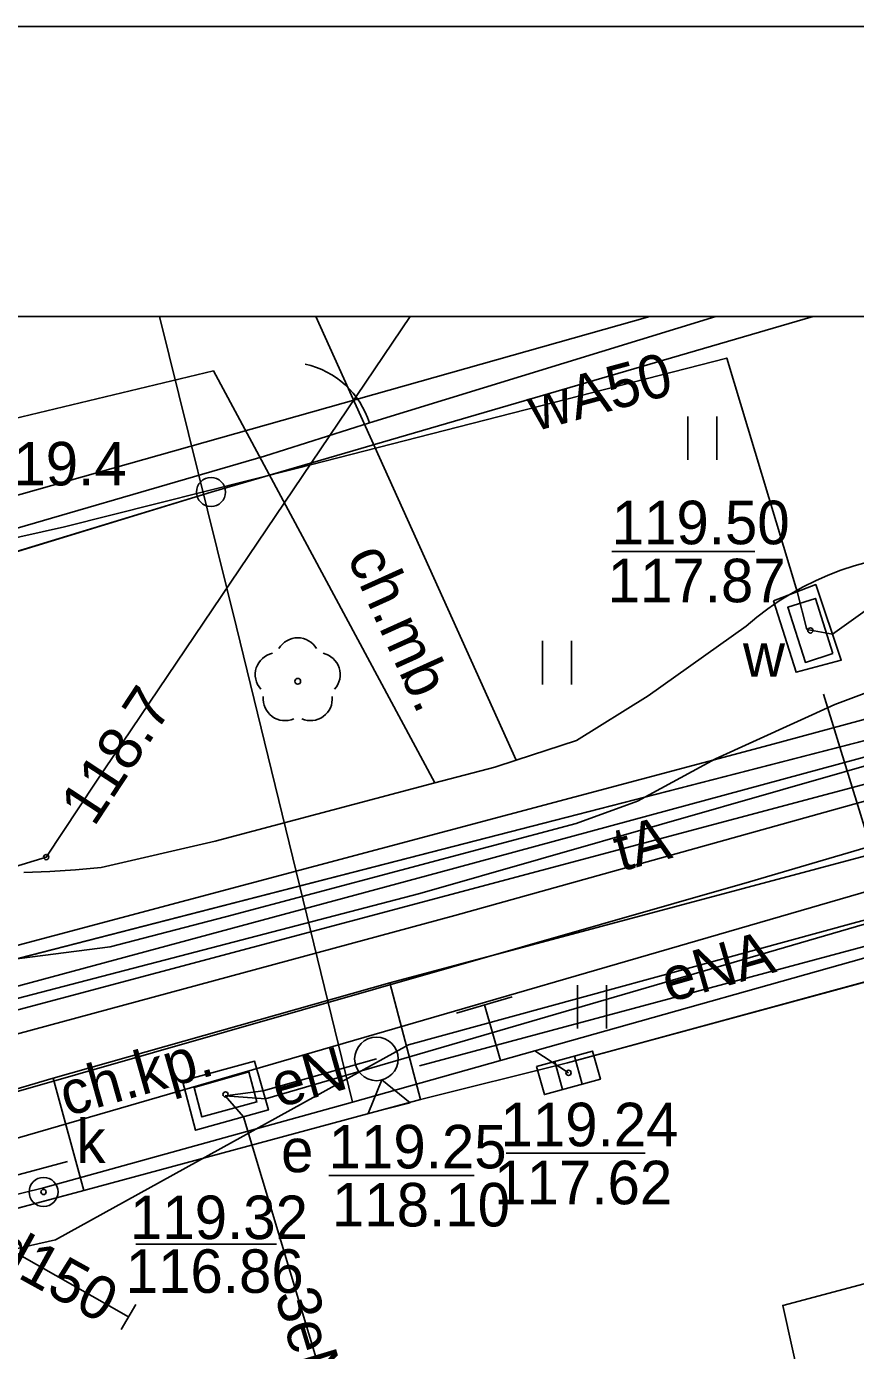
# Model space of a CAD drawing. Extents: x 6432121 to 6432331, y 5662538 to 5662686.
# Drawn here: x 6432203.86 to 6432218.14, y 5662663.23 to 5662686.05 of the extents above; entities that cross this region are included whole.
import ezdxf

# ---------------------------------------------------------------- set-up
doc = ezdxf.new("R2010")
doc.units = 0
for name, color, linetype in [('Warstwa 1', 7, 'Continuous'), ('Warstwa 10', 7, 'Continuous'), ('Warstwa 11', 7, 'Continuous'), ('Warstwa 12', 7, 'Continuous'), ('Warstwa 13', 7, 'Continuous'), ('Warstwa 14', 7, 'Continuous'), ('Warstwa 15', 7, 'Continuous'), ('Warstwa 16', 7, 'Continuous'), ('Warstwa 19', 7, 'Continuous'), ('Warstwa 2', 7, 'Continuous'), ('Warstwa 20', 7, 'Continuous'), ('Warstwa 3', 7, 'Continuous'), ('Warstwa 4', 7, 'Continuous'), ('Warstwa 40', 7, 'Continuous'), ('Warstwa 5', 7, 'Continuous'), ('Warstwa 6', 7, 'Continuous'), ('Warstwa 63', 7, 'Continuous'), ('Warstwa 8', 7, 'Continuous'), ('Warstwa 9', 7, 'Continuous')]:
    doc.layers.add(name, color=color, linetype=linetype)

msp = doc.modelspace()

# ---------------------------------------------------------------- linework, layer by layer
at = {"layer": 'Warstwa 1'}
for p, q in [((6432207.04, 5662678.03), (6432217.416, 5662681.053)), ((6432207.04, 5662678.03), (6432217.416, 5662681.053)), ((6432136.78, 5662656.51), (6432207.04, 5662678.03)), ((6432136.78, 5662656.51), (6432207.04, 5662678.03)), ((6432183.398, 5662664.76), (6432232.544, 5662677.413)), ((6432183.398, 5662664.76), (6432232.544, 5662677.413))]:
    msp.add_line(p, q, dxfattribs=at)
at = {"layer": 'Warstwa 10'}
for points in [[(6432178.835, 5662663.483), (6432179.667, 5662663.685), (6432183.376, 5662664.411), (6432187.121, 5662665.475), (6432194.656, 5662667.652), (6432202.136, 5662669.801), (6432216.655, 5662673.667), (6432220.668, 5662674.754), (6432223.415, 5662675.469), (6432239.794, 5662679.846), (6432240.486, 5662681.053)], [(6432125.976, 5662657.54), (6432137.66, 5662651.5), (6432142.32, 5662652.91), (6432165.05, 5662658.98), (6432185.52, 5662663.77), (6432211.24, 5662670.73), (6432230.88, 5662676.21), (6432235.66, 5662674.65)]]:
    msp.add_lwpolyline(points, dxfattribs=at)
msp.add_circle((6432207.04, 5662678.03), 0.25, dxfattribs=at)
at = {"layer": 'Warstwa 11'}
msp.add_circle((6432208.534, 5662674.768), 0.05, dxfattribs=at)
for centre, start, end in [((6432208.534, 5662675.143), 30.1471, 149.8529), ((6432208.177, 5662674.884), 102.1471, 221.8529), ((6432208.891, 5662674.884), 318.1471, 77.8529), ((6432208.314, 5662674.465), 174.1471, 293.8529), ((6432208.754, 5662674.465), 246.1471, 5.8529)]:
    msp.add_arc(centre, 0.375, start, end, dxfattribs=at)
at = {"layer": 'Warstwa 12'}
for points in [[(6432210.47, 5662681.053), (6432205.055, 5662673.029), (6432204.2, 5662671.738), (6432181.234, 5662664.72), (6432157.763, 5662657.531), (6432142.635, 5662652.934), (6432138.113, 5662652.263), (6432131.596, 5662652.74), (6432125.976, 5662654.881)], [(6432252.82, 5662681.053), (6432221.047, 5662671.933), (6432138.764, 5662648.032), (6432132.495, 5662646.498), (6432126.708, 5662647.568), (6432125.976, 5662647.734)], [(6432236.687, 5662681.053), (6432236.179, 5662680.268), (6432235.997, 5662679.964), (6432233.762, 5662674.712), (6432226.676, 5662672.867), (6432218.17, 5662670.615), (6432210.443, 5662668.5), (6432204.363, 5662665.144), (6432201.056, 5662664.395), (6432197.485, 5662663.542), (6432196.233, 5662663.213), (6432189.469, 5662661.315), (6432178.042, 5662658.146), (6432174.146, 5662657.07), (6432174.002, 5662656.976), (6432170.36, 5662653.903), (6432162.21, 5662651.482), (6432158.665, 5662650.451), (6432153.815, 5662649.037)], [(6432161.551, 5662681.053), (6432167.819, 5662674.322), (6432168.955, 5662673.173), (6432173.894, 5662667.86), (6432175.535, 5662666.115), (6432175.942, 5662663.535), (6432176.507, 5662663.465), (6432178.7, 5662662.668), (6432179.059, 5662662.663), (6432183.548, 5662663.582), (6432184.625, 5662663.866), (6432192.37, 5662666.167), (6432200.892, 5662668.754), (6432210.964, 5662671.473), (6432222.171, 5662674.51), (6432232.177, 5662677.188), (6432233.223, 5662677.473), (6432238.797, 5662677.192), (6432240.154, 5662672.977), (6432241.644, 5662668.194), (6432242.191, 5662665.717), (6432243.645, 5662658.765)], [(6432214.6, 5662681.053), (6432203.235, 5662677.843), (6432183.955, 5662671.923), (6432183.557, 5662671.545)], [(6432248.82, 5662629.93), (6432248.54, 5662629.72), (6432247.48, 5662630.2), (6432247.186, 5662630.33), (6432247.012, 5662630.407), (6432246.73, 5662630.84), (6432246.374, 5662630.582), (6432219.55, 5662620.66), (6432213.49, 5662610.33), (6432213.18, 5662609.798), (6432212.84, 5662609.97), (6432201.94, 5662619.39), (6432188.48, 5662659.63), (6432188.372, 5662660.264), (6432188.26, 5662660.96), (6432187.54, 5662663.58), (6432189.456, 5662664.144), (6432190.073, 5662664.038), (6432190.591, 5662664.478), (6432199.77, 5662667.18), (6432202.78, 5662668.86), (6432236.07, 5662677.73), (6432238.751, 5662681.053)], [(6432206.153, 5662681.053), (6432207.481, 5662675.701), (6432209.479, 5662667.515)], [(6432225.358, 5662681.053), (6432223.45, 5662679.654), (6432217.748, 5662675.581), (6432217.308, 5662675.659)], [(6432217.308, 5662675.659), (6432217.142, 5662676.313), (6432215.927, 5662680.339), (6432208.528, 5662678.44), (6432204.518, 5662677.431), (6432201.816, 5662676.824), (6432201.263, 5662678.637)], [(6432250.716, 5662679.086), (6432250.106, 5662678.913), (6432243.339, 5662677.004), (6432243.112, 5662676.943), (6432234.209, 5662674.451), (6432226.12, 5662672.203), (6432219.693, 5662670.39), (6432212.03, 5662668.231), (6432209.479, 5662667.515)], [(6432126.82, 5662648.145), (6432127.178, 5662648.008), (6432131.097, 5662647.505), (6432133.122, 5662647.201), (6432135.028, 5662647.845), (6432148.121, 5662651.554), (6432159.913, 5662655.046), (6432176.332, 5662659.768), (6432190.085, 5662663.807), (6432202.171, 5662667.26), (6432216.316, 5662671.31), (6432225.518, 5662674.016), (6432231.508, 5662675.69), (6432243.068, 5662679.006)], [(6432129.02, 5662644.49), (6432128.8, 5662645.29), (6432133.76, 5662648.23), (6432151.52, 5662653.14), (6432168.26, 5662658.24), (6432174.11, 5662659.65), (6432182.72, 5662662.19), (6432184.64, 5662664.15), (6432186.13, 5662664.58), (6432196.49, 5662667.42), (6432210.64, 5662671.11), (6432218.98, 5662673.5), (6432219.48, 5662674.07), (6432230.96, 5662676.8), (6432232.45, 5662677.97)], [(6432232.59, 5662674.745), (6432231.97, 5662674.57), (6432207.98, 5662667.57), (6432207.285, 5662667.626)], [(6432217.592, 5662674.545), (6432218.677, 5662671.027), (6432220.558, 5662664.988)], [(6432213.2, 5662668.02), (6432212.621, 5662668.398)], [(6432207.285, 5662667.626), (6432207.94, 5662667.71), (6432209.89, 5662668.26)], [(6432125.976, 5662645.74), (6432131.623, 5662647.083), (6432138.492, 5662648.808), (6432146.028, 5662650.541), (6432153.864, 5662652.39), (6432160.763, 5662654.062), (6432162.516, 5662654.48), (6432167.591, 5662655.857), (6432175.21, 5662658.015), (6432175.71, 5662658.12), (6432181.929, 5662659.868), (6432191.24, 5662662.505), (6432195.372, 5662663.644), (6432202.44, 5662665.619), (6432204.153, 5662666.037), (6432209.479, 5662667.515)], [(6432207.285, 5662667.626), (6432207.6, 5662667.26), (6432209.85, 5662659.78), (6432209.785, 5662659.335)], [(6432202.44, 5662665.619), (6432205.619, 5662663.813)], [(6432220.558, 5662664.988), (6432216.892, 5662664.011), (6432217.526, 5662661.155)]]:
    msp.add_lwpolyline(points, dxfattribs=at)
at = {"layer": 'Warstwa 14'}
for p, q in [((6432213.947, 5662677.005), (6432216.41, 5662677.005)), ((6432214.519, 5662666.635), (6432212.127, 5662666.635)), ((6432209.072, 5662666.248), (6432211.574, 5662666.248)), ((6432205.743, 5662665.068), (6432208.166, 5662665.068))]:
    msp.add_line(p, q, dxfattribs=at)
for centre in [(6432217.367, 5662675.645), (6432217.367, 5662675.645), (6432204.2, 5662671.738), (6432213.2, 5662668.02), (6432207.29, 5662667.647), (6432204.155, 5662665.967), (6432204.155, 5662665.967)]:
    msp.add_circle(centre, 0.045, dxfattribs=at)
at = {"layer": 'Warstwa 16'}
for points in [[(6432216.733, 5662676.157), (6432217.46, 5662676.436), (6432217.899, 5662675.132), (6432217.122, 5662674.923)], [(6432206.55, 5662667.88), (6432207.79, 5662668.22), (6432208.03, 5662667.38), (6432206.77, 5662667.03)]]:
    msp.add_lwpolyline(points, close=True, dxfattribs=at)
at = {"layer": 'Warstwa 19'}
for p, q in [((6432211.27, 5662669.051), (6432212.23, 5662669.331)), ((6432212.03, 5662668.231), (6432211.75, 5662669.191))]:
    msp.add_line(p, q, dxfattribs=at)
at = {"layer": 'Warstwa 2'}
for points in [[(6432209.77, 5662679.22), (6432215.737, 5662681.053)], [(6432201.9, 5662678.817), (6432202.47, 5662677.05), (6432207.96, 5662678.65)], [(6432210.63, 5662668.14), (6432237.94, 5662675.47), (6432239.56, 5662678.35)], [(6432204.57, 5662666.49), (6432179.48, 5662659.74), (6432149.1, 5662650.42)]]:
    msp.add_lwpolyline(points, dxfattribs=at)
at = {"layer": 'Warstwa 20'}
msp.add_line((6432205.745, 5662664.029), (6432205.493, 5662663.597), dxfattribs=at)
at = {"layer": 'Warstwa 3'}
msp.add_lwpolyline([(6432207.96, 5662678.65), (6432209.77, 5662679.22)], dxfattribs=at)
msp.add_arc((6432208.339, 5662678.769), 1.5, 17.4814, 77.4814, dxfattribs=at)
at = {"layer": 'Warstwa 4'}
for p, q in [((6432212.965, 5662668.214), (6432213.098, 5662667.732)), ((6432213.302, 5662668.308), (6432213.435, 5662667.826))]:
    msp.add_line(p, q, dxfattribs=at)
for points in [[(6432217.757, 5662675.245), (6432217.453, 5662676.197), (6432216.977, 5662676.045), (6432217.281, 5662675.093)], [(6432212.651, 5662668.127), (6432213.615, 5662668.395), (6432213.749, 5662667.913), (6432212.785, 5662667.645)], [(6432206.75, 5662667.77), (6432207.69, 5662668.04), (6432207.83, 5662667.52), (6432206.88, 5662667.26)]]:
    msp.add_lwpolyline(points, close=True, dxfattribs=at)
msp.add_circle((6432204.155, 5662665.967), 0.25, dxfattribs=at)
at = {"layer": 'Warstwa 40'}
msp.add_lwpolyline([(6432209.983, 5662667.897), (6432210.471, 5662667.506), (6432209.745, 5662667.319)], close=True, dxfattribs=at)
msp.add_circle((6432209.89, 5662668.26), 0.375, dxfattribs=at)
at = {"layer": 'Warstwa 5'}
for p, q in [((6432208.846, 5662681.053), (6432212.299, 5662673.411)), ((6432203.254, 5662679.202), (6432207.083, 5662680.119)), ((6432207.083, 5662680.119), (6432210.898, 5662673.016)), ((6432215.254, 5662678.584), (6432215.254, 5662679.334)), ((6432215.754, 5662678.584), (6432215.754, 5662679.334)), ((6432218.12, 5662676.76), (6432223.92, 5662678.34)), ((6432217.454, 5662676.5), (6432217.672, 5662676.597)), ((6432217.672, 5662676.597), (6432217.894, 5662676.684)), ((6432217.894, 5662676.684), (6432218.12, 5662676.76)), ((6432217.032, 5662676.277), (6432217.241, 5662676.394)), ((6432217.241, 5662676.394), (6432217.454, 5662676.5)), ((6432216.633, 5662676.017), (6432216.83, 5662676.152)), ((6432216.83, 5662676.152), (6432217.032, 5662676.277)), ((6432216.26, 5662675.72), (6432216.443, 5662675.873)), ((6432216.443, 5662675.873), (6432216.633, 5662676.017)), ((6432214.57, 5662674.52), (6432216.26, 5662675.72)), ((6432212.752, 5662674.715), (6432212.752, 5662675.465)), ((6432213.252, 5662674.715), (6432213.252, 5662675.465)), ((6432213.18, 5662668.19), (6432238.51, 5662675.09)), ((6432213.18, 5662668.19), (6432238.51, 5662675.09)), ((6432213.34, 5662673.75), (6432214.57, 5662674.52)), ((6432210.12, 5662669.57), (6432225.69, 5662673.73)), ((6432210.12, 5662669.57), (6432225.69, 5662673.73)), ((6432212.299, 5662673.411), (6432213.34, 5662673.75)), ((6432207.11, 5662672.01), (6432210.898, 5662673.016)), ((6432205.15, 5662671.56), (6432207.11, 5662672.01)), ((6432204.706, 5662671.518), (6432205.15, 5662671.56)), ((6432203.816, 5662671.471), (6432204.261, 5662671.488)), ((6432204.261, 5662671.488), (6432204.706, 5662671.518)), ((6432204.32, 5662667.93), (6432210.12, 5662669.57)), ((6432210.12, 5662669.57), (6432210.65, 5662667.56)), ((6432213.354, 5662668.783), (6432213.354, 5662669.533)), ((6432213.854, 5662668.783), (6432213.854, 5662669.533)), ((6432210.65, 5662667.56), (6432213.18, 5662668.19)), ((6432210.65, 5662667.56), (6432213.18, 5662668.19)), ((6432127.12, 5662644.89), (6432204.32, 5662667.93)), ((6432204.85, 5662665.99), (6432210.65, 5662667.56)), ((6432198.79, 5662664.37), (6432204.85, 5662665.99))]:
    msp.add_line(p, q, dxfattribs=at)
at = {"layer": 'Warstwa 6'}
for points in [[(6432139.86, 5662681.053), (6432132.84, 5662660.45), (6432136.78, 5662656.51), (6432207.04, 5662678.03), (6432217.416, 5662681.053)], [(6432217.416, 5662681.053), (6432207.04, 5662678.03), (6432136.78, 5662656.51), (6432134.43, 5662655.74), (6432136.954, 5662653.004), (6432164.325, 5662660.371), (6432183.398, 5662664.76), (6432232.544, 5662677.413), (6432235.366, 5662681.053)], [(6432164.06, 5662654.4), (6432171.72, 5662656.75), (6432178.39, 5662658.77), (6432185.89, 5662660.86), (6432198.79, 5662664.37), (6432204.85, 5662665.99), (6432210.65, 5662667.56), (6432213.18, 5662668.19), (6432238.51, 5662675.09), (6432238.854, 5662675.652), (6432239.185, 5662676.222), (6432239.503, 5662676.799), (6432239.808, 5662677.384), (6432240.099, 5662677.975), (6432240.377, 5662678.572), (6432240.642, 5662679.176), (6432240.893, 5662679.785), (6432241.13, 5662680.4), (6432241.403, 5662681.053)]]:
    msp.add_lwpolyline(points, dxfattribs=at)
msp.add_lwpolyline([(6432234.842, 5662644.244), (6432245.39, 5662639.916), (6432244.087, 5662648.722), (6432241.262, 5662679.658), (6432232.544, 5662677.413), (6432183.398, 5662664.76), (6432164.325, 5662660.371), (6432136.954, 5662653.004), (6432141.907, 5662600.47), (6432147.05, 5662605.45), (6432164.332, 5662622.19), (6432166.394, 5662623.975)], close=True, dxfattribs=at)
at = {"layer": 'Warstwa 63'}
for points in [[(6432120.976, 5662686.053), (6432330.976, 5662686.053), (6432330.976, 5662537.553), (6432120.976, 5662537.553)], [(6432125.976, 5662556.053), (6432325.976, 5662556.053), (6432325.976, 5662681.053), (6432125.976, 5662681.053)]]:
    msp.add_lwpolyline(points, close=True, dxfattribs=at)
at = {"layer": 'Warstwa 8'}
for p, q in [((6432213.18, 5662668.19), (6432238.51, 5662675.09)), ((6432210.65, 5662667.56), (6432213.18, 5662668.19)), ((6432204.85, 5662665.99), (6432210.65, 5662667.56)), ((6432198.79, 5662664.37), (6432204.85, 5662665.99))]:
    msp.add_line(p, q, dxfattribs=at)
at = {"layer": 'Warstwa 9'}
for p, q in [((6432208.846, 5662681.053), (6432212.299, 5662673.411)), ((6432203.254, 5662679.202), (6432207.083, 5662680.119)), ((6432207.083, 5662680.119), (6432210.898, 5662673.016)), ((6432218.12, 5662676.76), (6432223.92, 5662678.34)), ((6432217.454, 5662676.5), (6432217.672, 5662676.597)), ((6432217.672, 5662676.597), (6432217.894, 5662676.684)), ((6432217.894, 5662676.684), (6432218.12, 5662676.76)), ((6432217.032, 5662676.277), (6432217.241, 5662676.394)), ((6432217.241, 5662676.394), (6432217.454, 5662676.5)), ((6432216.633, 5662676.017), (6432216.83, 5662676.152)), ((6432216.83, 5662676.152), (6432217.032, 5662676.277)), ((6432216.26, 5662675.72), (6432216.443, 5662675.873)), ((6432216.443, 5662675.873), (6432216.633, 5662676.017)), ((6432214.57, 5662674.52), (6432216.26, 5662675.72)), ((6432217.79, 5662674.37), (6432219.75, 5662675.1)), ((6432217.79, 5662674.37), (6432219.75, 5662675.1)), ((6432213.34, 5662673.75), (6432214.57, 5662674.52)), ((6432215.73, 5662673.43), (6432217.79, 5662674.37)), ((6432215.73, 5662673.43), (6432217.79, 5662674.37)), ((6432210.12, 5662669.57), (6432225.69, 5662673.73)), ((6432212.299, 5662673.411), (6432213.34, 5662673.75)), ((6432211.93, 5662673.29), (6432212.299, 5662673.411)), ((6432211.93, 5662673.29), (6432212.299, 5662673.411)), ((6432214.39, 5662672.7), (6432215.73, 5662673.43)), ((6432214.39, 5662672.7), (6432215.73, 5662673.43)), ((6432210.898, 5662673.016), (6432211.93, 5662673.29)), ((6432210.898, 5662673.016), (6432211.93, 5662673.29)), ((6432207.11, 5662672.01), (6432210.898, 5662673.016)), ((6432213.33, 5662672.32), (6432214.39, 5662672.7)), ((6432213.33, 5662672.32), (6432214.39, 5662672.7)), ((6432207.29, 5662670.71), (6432213.33, 5662672.32)), ((6432207.29, 5662670.71), (6432213.33, 5662672.32)), ((6432205.15, 5662671.56), (6432207.11, 5662672.01)), ((6432204.706, 5662671.518), (6432205.15, 5662671.56)), ((6432203.816, 5662671.471), (6432204.261, 5662671.488)), ((6432204.261, 5662671.488), (6432204.706, 5662671.518)), ((6432205.3, 5662670.19), (6432207.29, 5662670.71)), ((6432205.3, 5662670.19), (6432207.29, 5662670.71)), ((6432203.56, 5662669.97), (6432205.3, 5662670.19)), ((6432203.56, 5662669.97), (6432205.3, 5662670.19)), ((6432204.32, 5662667.93), (6432210.12, 5662669.57)), ((6432204.32, 5662667.93), (6432210.12, 5662669.57)), ((6432210.12, 5662669.57), (6432210.65, 5662667.56)), ((6432127.12, 5662644.89), (6432204.32, 5662667.93)), ((6432204.32, 5662667.93), (6432204.85, 5662665.99)), ((6432204.85, 5662665.99), (6432210.65, 5662667.56))]:
    msp.add_line(p, q, dxfattribs=at)

# ---------------------------------------------------------------- texts
at = {"layer": 'Warstwa 13'}
for s, rotation, p in [('wA50', 15.0917, (6432212.622, 5662679.073)), ('tA', 14.9198, (6432214.098, 5662671.487)), ('eNA', 16.0027, (6432214.929, 5662669.228)), ('eN', 15.7506, (6432208.202, 5662667.414)), ('kd150', 331.1009, (6432202.759, 5662665.012)), ('3eN', 286.7425, (6432208.132, 5662664.19))]:
    msp.add_text(s, height=0.75, rotation=rotation, dxfattribs=at).set_placement(p)
msp.add_text('119.4', height=0.75, dxfattribs=at).set_placement((6432203.076, 5662678.144))
at = {"layer": 'Warstwa 14'}
for s, p in [('117.87', (6432213.874, 5662676.13)), ('117.62', (6432211.92, 5662665.755)), ('118.10', (6432209.124, 5662665.373)), ('116.86', (6432205.57, 5662664.228))]:
    msp.add_text(s, height=0.75, dxfattribs=at).set_placement(p)
msp.add_text('118.7', height=0.75, rotation=56.677, dxfattribs=at).set_placement((6432205.024, 5662672.244))
at = {"layer": 'Warstwa 15'}
for s, p in [('119.50', (6432213.943, 5662677.13)), ('119.24', (6432212.027, 5662666.755)), ('119.25', (6432209.066, 5662666.373)), ('119.32', (6432205.643, 5662665.155))]:
    msp.add_text(s, height=0.75, dxfattribs=at).set_placement(p)
at = {"layer": 'Warstwa 5'}
for s, p in [('w', (6432216.206, 5662674.848)), ('k', (6432204.72, 5662666.468)), ('e', (6432208.247, 5662666.308))]:
    msp.add_text(s, height=0.75, dxfattribs=at).set_placement(p)
at = {"layer": 'Warstwa 9'}
for s, rotation, p in [('ch.mb.', 294.317, (6432209.376, 5662676.916)), ('ch.kp.', 15.7907, (6432204.557, 5662667.267))]:
    msp.add_text(s, height=0.75, rotation=rotation, dxfattribs=at).set_placement(p)

doc.saveas('drawing.dxf')
